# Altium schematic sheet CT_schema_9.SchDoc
size 277 x 170 mm
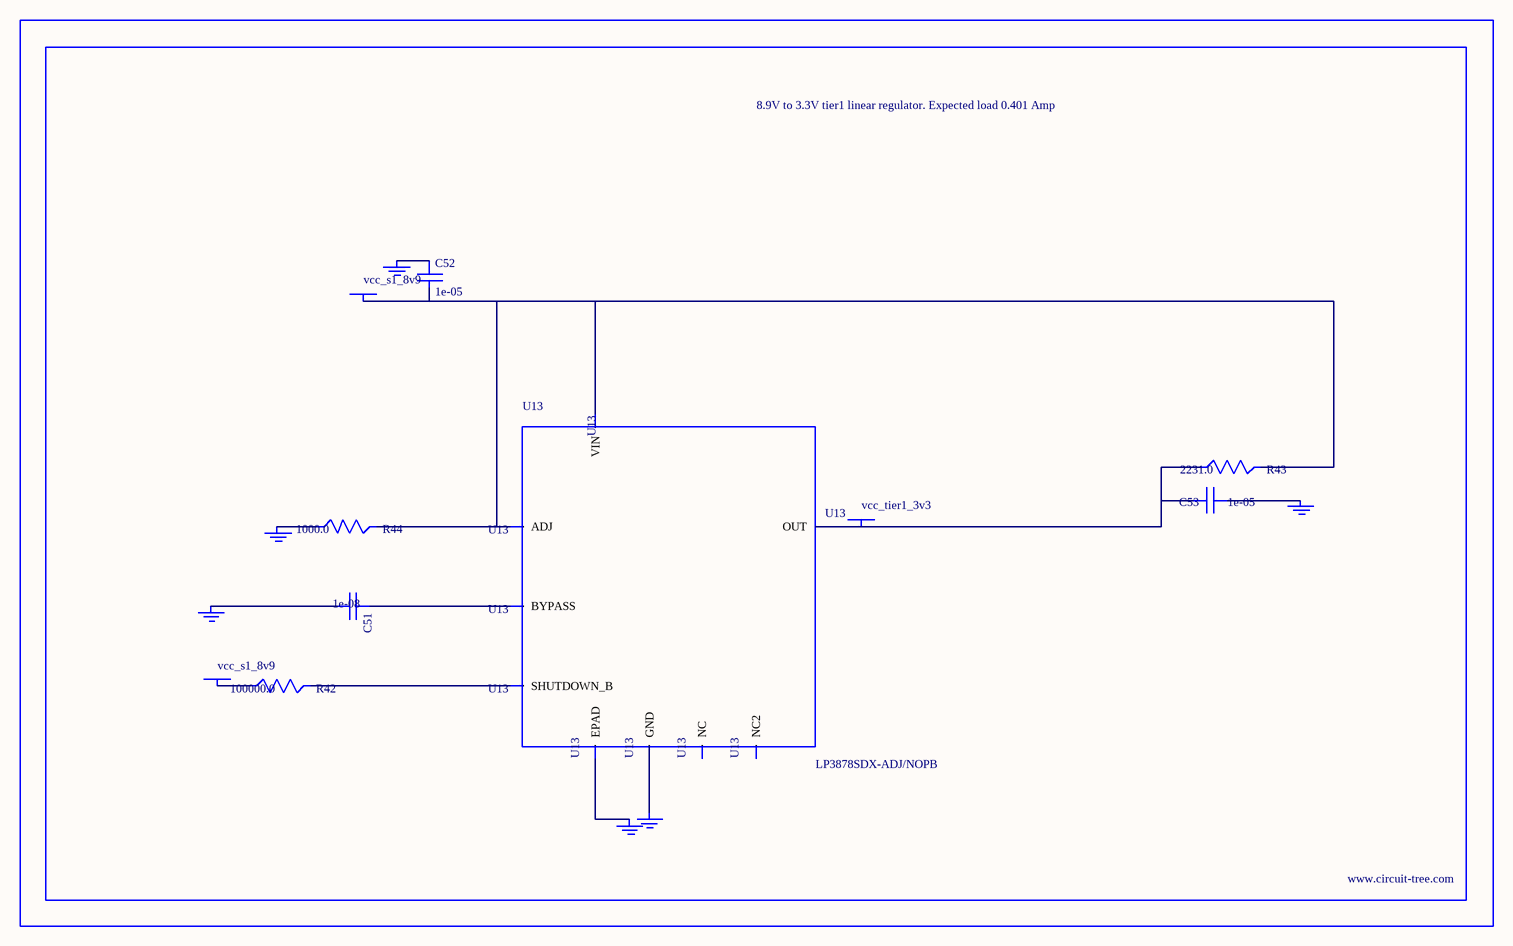
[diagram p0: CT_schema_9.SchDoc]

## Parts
BORDER8  (no value)
C51  1e-08  [C0402]
C52  1e-05  [C1206]
C53  1e-05  [C1210]
GND_INSTANCE_8_0  (no value)
GND_INSTANCE_8_1  (no value)
GND_INSTANCE_8_2  (no value)
GND_INSTANCE_8_3  (no value)
GND_INSTANCE_8_4  (no value)
GND_INSTANCE_8_5  (no value)
POWER_INSTANCE_8_0  vcc_s1_8v9
POWER_INSTANCE_8_1  vcc_s1_8v9
POWER_INSTANCE_8_2  vcc_tier1_3v3
R42  100000.0  [R0603]
R43  2231.0  [R0603]
R44  1000.0  [R0603]
U13  LP3878SDX-ADJ/NOPB  [WSON-8]

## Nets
NetC51_1: C51.1 U13.1(BYPASS)
NetC51_2: C51.2 GND_INSTANCE_8_0.0(GND)
NetC52_1: C52.1 GND_INSTANCE_8_1.0(GND)
NetC52_2: C52.2 POWER_INSTANCE_8_0.0(PWR) R43.2 R44.2 U13.4(VIN) U13.6(ADJ)
NetC53_1: C53.1 GND_INSTANCE_8_2.0(GND)
NetC53_2: C53.2 POWER_INSTANCE_8_2.0(PWR) R43.1 U13.5(OUT)
NetGND_INSTANCE_8_3_0: GND_INSTANCE_8_3.0(GND) R44.1
NetGND_INSTANCE_8_4_0: GND_INSTANCE_8_4.0(GND) U13.PAD(EPAD)
NetGND_INSTANCE_8_5_0: GND_INSTANCE_8_5.0(GND) U13.3(GND)
NetPOWER_INSTANCE_8_1_0: POWER_INSTANCE_8_1.0(PWR) R42.1
NetR42_2: R42.2 U13.8(SHUTDOWN_B)

Not connected (* = marked no-connect by the designer): U13 2(NC) 7(NC2)

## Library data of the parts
BORDER8 = BORDER_PAGE8
C51 = C0402C103K3RAC
C52 = C1206C106K3RACTU
C53 = GRM32DR61E106MA12L
GND_INSTANCE_8_0-GND_INSTANCE_8_5 = GND
POWER_INSTANCE_8_0-POWER_INSTANCE_8_2 = PWR
R42 = RC0603JR-07100KL
R43 = R43
R44 = RC0603JR-071KL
